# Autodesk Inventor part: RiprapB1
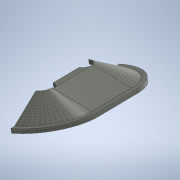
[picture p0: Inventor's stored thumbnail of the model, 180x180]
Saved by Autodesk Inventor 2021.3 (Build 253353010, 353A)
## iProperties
Created: 2021-11
Part Number: RiprapB1
Material: Generic
Document SubType Name: Modeling
Designer: u1426
Density: 1 g/cm^3
Appearance: Rubble - River Rock
Author: u1426
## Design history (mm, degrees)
sketch "Sketch1"
  geometry: L1 (1207.008, -914.4)-(1394.474, -2788.948); L2 (1394.474, -2788.948)-(5858.256, -11716.512); L3 (5858.256, -13024.651)-(6925.056, -13024.651); L4 (6925.056, -13024.651)-(6925.056, -11805.451); L5 (6925.056, -11805.451)-(2287.591, -2530.521); L6 (2287.591, -2530.521)-(2125.969, -914.4); L7 (2125.969, -914.4)-(1207.008, -914.4); L8 (1394.474, -2788.948)-(0, 0); L9 (1207.008, 0)-(0, 0); L10 (5858.256, -13024.651)-(5858.256, -11716.512); L11 (1207.008, 0)-(1207.008, -914.4)
  constraints: 22 end point, 2 horizontal, 2 parallel, 2 perpendicular, 2 vertical, 1 collinear, 1 other
  dimensions: "d0" = 1066.8 distance of L3.start L3.end; "d1" = 1219.2 distance of L3.end L4.end; "d2" = 914.4 distance between parallel lines of L5 L2; "d3" = 914.4 distance between parallel lines of L6 L1; "d20" = 84.2891 deg angle of L1 L7; "d23" = 1207.008 distance of L9.start L8.end; "d24" = 63.4349 deg angle of L8 L9; "d25" = 5858.256 distance from line of L8.end L10 (= SpillPtElev - ToeElev); "d26" = 1874.54794 vertical distance of L1.start L1.end (derived); "d27" = 11716.512 distance from line of L9 L2.end (derived); "d28" = 914.4 distance between parallel lines of L9 L7
extrude "Extrusion1" new body sketch "Sketch1" stored distance "d8" = 14935.2; taper "d9" = 0 deg
sketch "Sketch2"
  geometry: L1 (0, 0)-(-4569.376, 0); L2 (-5858.256, -11716.512)-(-1394.474, -2788.948) reference; L3 (-2287.591, -2530.521)-(-6925.056, -11805.451) reference; L4 (-6925.056, -11805.451)-(-6925.056, -13024.651) reference; L5 (-6925.056, -13024.651)-(-5858.256, -13024.651) reference; L6 (-5858.256, -13024.651)-(-5858.256, -11716.512) reference; L7 (-1394.474, -2788.948)-(-5858.256, -11716.512) reference; L8 (-1394.474, -2788.948)-(-1252.728, -2505.456); L9 (-1252.728, -2505.456)-(-2275.058, -2505.456); L10 (-2287.591, -2530.521)-(-2125.969, -914.4) reference; L11 (-2275.058, -2505.456)-(-2287.591, -2530.521)
  constraints: 8 end point, 2 collinear, 2 horizontal
  dimensions: "d29" = 4605.528 distance from line of L8.end L6 (= TopRRElev - ToeElev)
revolve "Revolution1" sketch "Sketch2" stored, may be unused: angle "d30" = 90 deg
sketch "Sketch3"
  geometry: L1 (-1394.474, 2788.948)-(-5858.256, 11716.512) reference; L2 (-6925.056, 11805.451)-(-2287.591, 2530.521) reference; L3 (-6925.056, 13024.651)-(-6925.056, 11805.451) reference; L4 (-5858.256, 13024.651)-(-6925.056, 13024.651) reference; L5 (-5858.256, 11716.512)-(-5858.256, 13024.651) reference; L6 (-1394.474, 2788.948)-(-1252.728, 2505.456) reference; L7 (-1252.728, 2505.456)-(-1366.123, 2505.456) reference; L8 (-2287.591, 2530.521)-(-2275.058, 2505.456) reference; L9 (0, 0)-(-4606.323, 0); L10 (-5858.256, 0)-(-1252.728, 0) reference; L11 (-2275.058, 2505.456)-(-1366.123, 2505.456) reference
  constraints: 2 end point, 1 point on line
revolve "Revolution2" sketch "Sketch3" stored, may be unused: angle "d31" = 90 deg
sketch "Sketch4"
  geometry: L1 (-7467.6, -2788.948)-(7467.6, -2788.948) reference; L2 (-7467.6, -11716.512)-(-7467.6, -2788.948) reference; L3 (0, 0)-(0, 4154.64); L4 (-7467.6, -2788.948)-(-7467.6, 0); L5 (-7467.6, 0)-(-4678.652, 0); L6 (7467.6, -2505.456)-(7467.6, -2788.948) reference; L7 (7467.6, -2788.948)-(7467.6, 0); L8 (7467.6, 0)-(4678.652, 0); A1 r 2788.948 centre (-7467.6, 0) between (-7467.6, -2788.948) and (-4678.652, 0); A2 r 2788.948 centre (7467.6, 0) between (4678.652, 0) and (7467.6, -2788.948); 1 further point
  constraints: 10 end point, 4 point on circle, 2 centre point, 2 perpendicular, 2 symmetric about line, 1 vertical, 1 other
  dimensions: "d33" = 2788.94794 radius of A1; "d34" = 7467.6 distance from line of L4.end L3
extrude "Extrusion2" cut sketch "Sketch4" extent not by distance; stored distance "d35" = 0; taper "d36" = 0 deg
body "Solid1"
other parameters: "TopRRCapElev" = 865464.36 [user parameter], "ToeElev" = 860813.112 [user parameter; used in 2 equation terms], "TopRRElev" = 865418.64 [user parameter; used in 1 equation term], "SpillPtElev" = 866671.368 [user parameter; used in 1 equation term]
